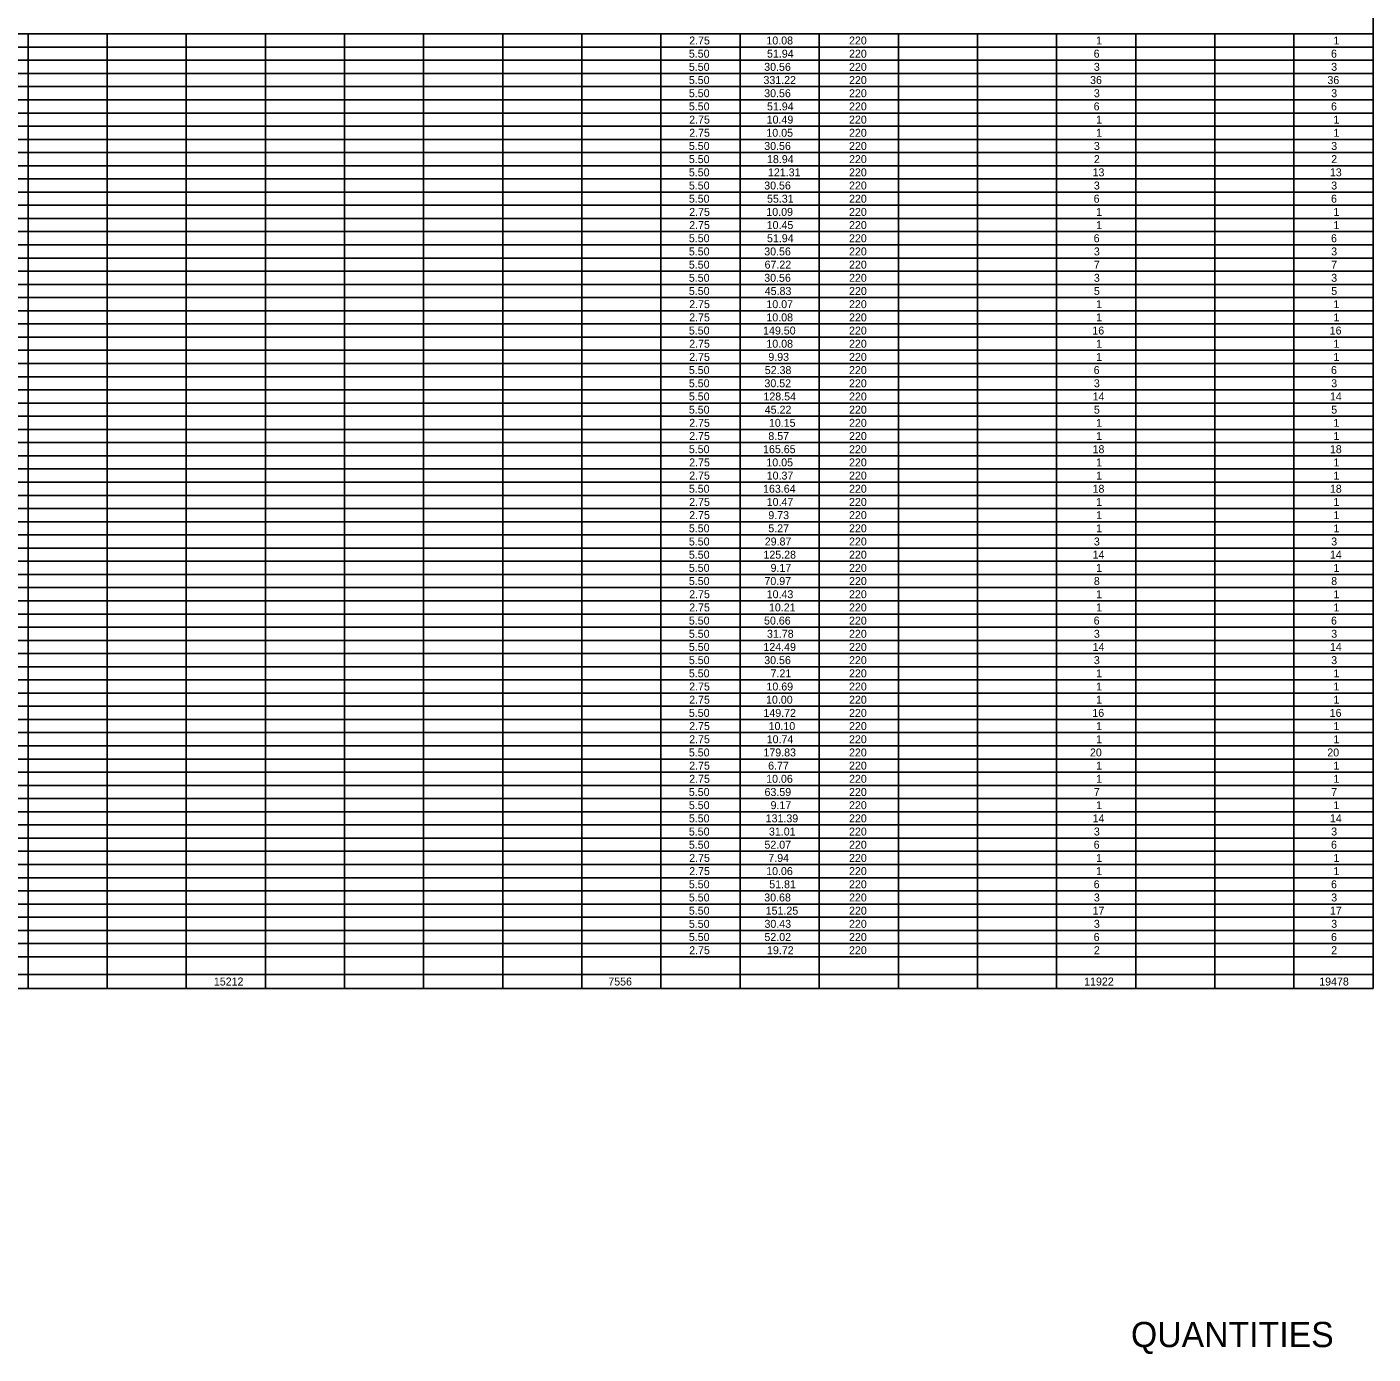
# Model space of a CAD drawing. Extents: x 1226590 to 1228573, y 151304 to 154224.
# Drawn here: x 1227485 to 1228151, y 151304 to 151961 of the extents above; entities that cross this region are included whole.
import ezdxf

# ---------------------------------------------------------------- set-up
doc = ezdxf.new("R2010")
doc.units = 0
doc.layers.add('R_Border Notes', color=7, linetype='Continuous')
doc.layers.add('R_Dimension', color=7, linetype='Continuous')

msp = doc.modelspace()

# ---------------------------------------------------------------- linework, layer by layer
at = {"layer": 'R_Dimension'}
for p, q in [((1228150.73, 151484.92), (1228150.73, 152182.03)), ((1226590.27, 151957.19), (1228150.73, 151957.19)), ((1227485.41, 151484.92), (1227485.41, 151957.19)), ((1227524.55, 151484.92), (1227524.55, 151957.19)), ((1227563.69, 151484.92), (1227563.69, 151957.19)), ((1227602.82, 151484.92), (1227602.82, 151957.19)), ((1227641.96, 151484.92), (1227641.96, 151957.19)), ((1227681.09, 151484.92), (1227681.09, 151957.19)), ((1227720.23, 151484.92), (1227720.23, 151957.19)), ((1227759.37, 151484.92), (1227759.37, 151957.19)), ((1227798.5, 151484.92), (1227798.5, 151957.19)), ((1227837.64, 151484.92), (1227837.64, 151957.19)), ((1227876.78, 151484.92), (1227876.78, 151957.19)), ((1227915.91, 151484.92), (1227915.91, 151957.19)), ((1227955.05, 151484.92), (1227955.05, 151957.19)), ((1227994.18, 151484.92), (1227994.18, 151957.19)), ((1228033.32, 151484.92), (1228033.32, 151957.19)), ((1228072.46, 151484.92), (1228072.46, 151957.19)), ((1228111.59, 151484.92), (1228111.59, 151957.19)), ((1226590.27, 151950.67), (1228150.73, 151950.67)), ((1226590.27, 151944.14), (1228150.73, 151944.14)), ((1226590.27, 151937.62), (1228150.73, 151937.62)), ((1226590.27, 151931.1), (1228150.73, 151931.1)), ((1226590.27, 151924.58), (1228150.73, 151924.58)), ((1226590.27, 151918.05), (1228150.73, 151918.05)), ((1226590.27, 151911.53), (1228150.73, 151911.53)), ((1226590.27, 151905.01), (1228150.73, 151905.01)), ((1226590.27, 151898.48), (1228150.73, 151898.48)), ((1226590.27, 151891.96), (1228150.73, 151891.96)), ((1226590.27, 151885.44), (1228150.73, 151885.44)), ((1226590.27, 151878.92), (1228150.73, 151878.92)), ((1226590.27, 151872.39), (1228150.73, 151872.39)), ((1226590.27, 151865.87), (1228150.73, 151865.87)), ((1226590.27, 151859.35), (1228150.73, 151859.35)), ((1226590.27, 151852.83), (1228150.73, 151852.83)), ((1226590.27, 151846.3), (1228150.73, 151846.3)), ((1226590.27, 151839.78), (1228150.73, 151839.78)), ((1226590.27, 151833.26), (1228150.73, 151833.26)), ((1226590.27, 151826.73), (1228150.73, 151826.73)), ((1226590.27, 151820.21), (1228150.73, 151820.21)), ((1226590.27, 151813.69), (1228150.73, 151813.69)), ((1226590.27, 151807.17), (1228150.73, 151807.17)), ((1226590.27, 151800.64), (1228150.73, 151800.64)), ((1226590.27, 151794.12), (1228150.73, 151794.12)), ((1226590.27, 151787.6), (1228150.73, 151787.6)), ((1226590.27, 151781.08), (1228150.73, 151781.08)), ((1226590.27, 151774.55), (1228150.73, 151774.55)), ((1226590.27, 151768.03), (1228150.73, 151768.03)), ((1226590.27, 151761.51), (1228150.73, 151761.51)), ((1226590.27, 151754.99), (1228150.73, 151754.99)), ((1226590.27, 151748.46), (1228150.73, 151748.46)), ((1226590.27, 151741.94), (1228150.73, 151741.94)), ((1226590.27, 151735.42), (1228150.73, 151735.42)), ((1226590.27, 151728.89), (1228150.73, 151728.89)), ((1226590.27, 151722.37), (1228150.73, 151722.37)), ((1226590.27, 151715.85), (1228150.73, 151715.85)), ((1226590.27, 151709.33), (1228150.73, 151709.33)), ((1226590.27, 151702.8), (1228150.73, 151702.8)), ((1226590.27, 151696.28), (1228150.73, 151696.28)), ((1226590.27, 151689.76), (1228150.73, 151689.76)), ((1226590.27, 151683.24), (1228150.73, 151683.24)), ((1226590.27, 151676.71), (1228150.73, 151676.71)), ((1226590.27, 151670.19), (1228150.73, 151670.19)), ((1226590.27, 151663.67), (1228150.73, 151663.67)), ((1226590.27, 151657.14), (1228150.73, 151657.14)), ((1226590.27, 151650.62), (1228150.73, 151650.62)), ((1226590.27, 151644.1), (1228150.73, 151644.1)), ((1226590.27, 151637.58), (1228150.73, 151637.58)), ((1226590.27, 151631.05), (1228150.73, 151631.05)), ((1226590.27, 151624.53), (1228150.73, 151624.53)), ((1226590.27, 151618.01), (1228150.73, 151618.01)), ((1226590.27, 151611.49), (1228150.73, 151611.49)), ((1226590.27, 151604.96), (1228150.73, 151604.96)), ((1226590.27, 151598.44), (1228150.73, 151598.44)), ((1226590.27, 151591.92), (1228150.73, 151591.92)), ((1226590.27, 151585.4), (1228150.73, 151585.4)), ((1226590.27, 151578.87), (1228150.73, 151578.87)), ((1226590.27, 151572.35), (1228150.73, 151572.35)), ((1226590.27, 151565.83), (1228150.73, 151565.83)), ((1226590.27, 151559.3), (1228150.73, 151559.3)), ((1226590.27, 151552.78), (1228150.73, 151552.78)), ((1226590.27, 151546.26), (1228150.73, 151546.26)), ((1226590.27, 151539.74), (1228150.73, 151539.74)), ((1226590.27, 151533.21), (1228150.73, 151533.21)), ((1226590.27, 151526.69), (1228150.73, 151526.69)), ((1226590.27, 151520.17), (1228150.73, 151520.17)), ((1226590.27, 151513.65), (1228150.73, 151513.65)), ((1226590.27, 151507.12), (1228150.73, 151507.12)), ((1226590.27, 151500.6), (1228150.73, 151500.6)), ((1226590.27, 151491.83), (1228150.75, 151491.83)), ((1226590.27, 151484.92), (1228150.75, 151484.92))]:
    msp.add_line(p, q, dxfattribs=at)

# ---------------------------------------------------------------- texts
at = {"layer": 'R_Border Notes'}
msp.add_text('QUANTITIES', height=12.5, dxfattribs=at).set_placement((1228030.98, 151307.48))
at = {"layer": 'R_Dimension'}
for s, height, p in [('2.75', 3.935, (1227812.46, 151951.96)), ('10.08', 3.935, (1227850.64, 151951.96)), ('220', 3.935, (1227891.52, 151951.96)), ('1', 3.94, (1228013.75, 151951.96)), ('1', 3.94, (1228131.16, 151951.96)), ('5.50', 3.935, (1227812.29, 151945.44)), ('51.94', 3.935, (1227850.95, 151945.44)), ('220', 3.935, (1227891.52, 151945.44)), ('6', 3.94, (1228012.53, 151945.44)), ('6', 3.94, (1228129.94, 151945.44)), ('5.50', 3.935, (1227812.29, 151938.91)), ('30.56', 3.935, (1227849.57, 151938.91)), ('220', 3.935, (1227891.52, 151938.91)), ('3', 3.94, (1228012.64, 151938.91)), ('3', 3.94, (1228130.04, 151938.91)), ('5.50', 3.935, (1227812.29, 151932.39)), ('331.22', 3.935, (1227849.18, 151932.39)), ('220', 3.935, (1227891.52, 151932.39)), ('36', 3.935, (1228010.76, 151932.39)), ('36', 3.935, (1228128.17, 151932.39)), ('5.50', 3.935, (1227812.29, 151925.87)), ('30.56', 3.935, (1227849.57, 151925.87)), ('220', 3.935, (1227891.52, 151925.87)), ('3', 3.94, (1228012.64, 151925.87)), ('3', 3.94, (1228130.04, 151925.87)), ('5.50', 3.935, (1227812.29, 151919.35)), ('51.94', 3.935, (1227850.95, 151919.35)), ('220', 3.935, (1227891.52, 151919.35)), ('6', 3.94, (1228012.53, 151919.35)), ('6', 3.94, (1228129.94, 151919.35)), ('2.75', 3.935, (1227812.46, 151912.82)), ('10.49', 3.935, (1227850.78, 151912.82)), ('220', 3.935, (1227891.52, 151912.82)), ('1', 3.94, (1228013.75, 151912.82)), ('1', 3.94, (1228131.16, 151912.82)), ('2.75', 3.935, (1227812.46, 151906.3)), ('10.05', 3.935, (1227850.64, 151906.3)), ('220', 3.935, (1227891.52, 151906.3)), ('1', 3.94, (1228013.75, 151906.3)), ('1', 3.94, (1228131.16, 151906.3)), ('5.50', 3.935, (1227812.29, 151899.78)), ('30.56', 3.935, (1227849.57, 151899.78)), ('220', 3.935, (1227891.52, 151899.78)), ('3', 3.94, (1228012.64, 151899.78)), ('3', 3.94, (1228130.04, 151899.78)), ('5.50', 3.935, (1227812.29, 151893.26)), ('18.94', 3.935, (1227850.95, 151893.26)), ('220', 3.935, (1227891.52, 151893.26)), ('2', 3.94, (1228012.64, 151893.26)), ('2', 3.94, (1228130.04, 151893.26)), ('5.50', 3.935, (1227812.29, 151886.73)), ('121.31', 3.935, (1227851.41, 151886.73)), ('220', 3.935, (1227891.52, 151886.73)), ('13', 3.935, (1228011.99, 151886.73)), ('13', 3.935, (1228129.39, 151886.73)), ('5.50', 3.935, (1227812.29, 151880.21)), ('30.56', 3.935, (1227849.57, 151880.21)), ('220', 3.935, (1227891.52, 151880.21)), ('3', 3.94, (1228012.64, 151880.21)), ('3', 3.94, (1228130.04, 151880.21)), ('5.50', 3.935, (1227812.29, 151873.69)), ('55.31', 3.935, (1227850.95, 151873.69)), ('220', 3.935, (1227891.52, 151873.69)), ('6', 3.94, (1228012.53, 151873.69)), ('6', 3.94, (1228129.94, 151873.69)), ('2.75', 3.935, (1227812.46, 151867.16)), ('10.09', 3.935, (1227850.62, 151867.16)), ('220', 3.935, (1227891.52, 151867.16)), ('1', 3.94, (1228013.75, 151867.16)), ('1', 3.94, (1228131.16, 151867.16)), ('2.75', 3.935, (1227812.46, 151860.64)), ('10.45', 3.935, (1227850.79, 151860.64)), ('220', 3.935, (1227891.52, 151860.64)), ('1', 3.94, (1228013.75, 151860.64)), ('1', 3.94, (1228131.16, 151860.64)), ('5.50', 3.935, (1227812.29, 151854.12)), ('51.94', 3.935, (1227850.95, 151854.12)), ('220', 3.935, (1227891.52, 151854.12)), ('6', 3.94, (1228012.53, 151854.12)), ('6', 3.94, (1228129.94, 151854.12)), ('5.50', 3.935, (1227812.29, 151847.6)), ('30.56', 3.935, (1227849.57, 151847.6)), ('220', 3.935, (1227891.52, 151847.6)), ('3', 3.94, (1228012.64, 151847.6)), ('3', 3.94, (1228130.04, 151847.6)), ('5.50', 3.935, (1227812.29, 151841.07)), ('67.22', 3.935, (1227849.74, 151841.07)), ('220', 3.935, (1227891.52, 151841.07)), ('7', 3.94, (1228012.64, 151841.07)), ('7', 3.94, (1228130.04, 151841.07)), ('5.50', 3.935, (1227812.29, 151834.55)), ('30.56', 3.935, (1227849.57, 151834.55)), ('220', 3.935, (1227891.52, 151834.55)), ('3', 3.94, (1228012.64, 151834.55)), ('3', 3.94, (1228130.04, 151834.55)), ('5.50', 3.935, (1227812.29, 151828.03)), ('45.83', 3.935, (1227849.83, 151828.03)), ('220', 3.935, (1227891.52, 151828.03)), ('5', 3.94, (1228012.64, 151828.03)), ('5', 3.94, (1228130.04, 151828.03)), ('2.75', 3.935, (1227812.46, 151821.51)), ('10.07', 3.935, (1227850.64, 151821.51)), ('220', 3.935, (1227891.52, 151821.51)), ('1', 3.94, (1228013.75, 151821.51)), ('1', 3.94, (1228131.16, 151821.51)), ('2.75', 3.935, (1227812.46, 151814.98)), ('10.08', 3.935, (1227850.64, 151814.98)), ('220', 3.935, (1227891.52, 151814.98)), ('1', 3.94, (1228013.75, 151814.98)), ('1', 3.94, (1228131.16, 151814.98)), ('5.50', 3.935, (1227812.29, 151808.46)), ('149.50', 3.935, (1227849.01, 151808.46)), ('220', 3.935, (1227891.52, 151808.46)), ('16', 3.935, (1228011.88, 151808.46)), ('16', 3.935, (1228129.29, 151808.46)), ('2.75', 3.935, (1227812.46, 151801.94)), ('10.08', 3.935, (1227850.64, 151801.94)), ('220', 3.935, (1227891.52, 151801.94)), ('1', 3.94, (1228013.75, 151801.94)), ('1', 3.94, (1228131.16, 151801.94)), ('2.75', 3.935, (1227812.46, 151795.42)), ('9.93', 3.935, (1227851.6, 151795.42)), ('220', 3.935, (1227891.52, 151795.42)), ('1', 3.94, (1228013.75, 151795.42)), ('1', 3.94, (1228131.16, 151795.42)), ('5.50', 3.935, (1227812.29, 151788.89)), ('52.38', 3.935, (1227849.83, 151788.89)), ('220', 3.935, (1227891.52, 151788.89)), ('6', 3.94, (1228012.53, 151788.89)), ('6', 3.94, (1228129.94, 151788.89)), ('5.50', 3.935, (1227812.29, 151782.37)), ('30.52', 3.935, (1227849.68, 151782.37)), ('220', 3.935, (1227891.52, 151782.37)), ('3', 3.94, (1228012.64, 151782.37)), ('3', 3.94, (1228130.04, 151782.37)), ('5.50', 3.935, (1227812.29, 151775.85)), ('128.54', 3.935, (1227849.18, 151775.85)), ('220', 3.935, (1227891.52, 151775.85)), ('14', 3.935, (1228011.99, 151775.85)), ('14', 3.935, (1228129.39, 151775.85)), ('5.50', 3.935, (1227812.29, 151769.32)), ('45.22', 3.935, (1227849.83, 151769.32)), ('220', 3.935, (1227891.52, 151769.32)), ('5', 3.94, (1228012.64, 151769.32)), ('5', 3.94, (1228130.04, 151769.32)), ('2.75', 3.935, (1227812.46, 151762.8)), ('10.15', 3.935, (1227851.91, 151762.8)), ('220', 3.935, (1227891.52, 151762.8)), ('1', 3.94, (1228013.75, 151762.8)), ('1', 3.94, (1228131.16, 151762.8)), ('2.75', 3.935, (1227812.46, 151756.28)), ('8.57', 3.935, (1227851.6, 151756.28)), ('220', 3.935, (1227891.52, 151756.28)), ('1', 3.94, (1228013.75, 151756.28)), ('1', 3.94, (1228131.16, 151756.28)), ('5.50', 3.935, (1227812.29, 151749.76)), ('165.65', 3.935, (1227849, 151749.76)), ('220', 3.935, (1227891.52, 151749.76)), ('18', 3.935, (1228011.99, 151749.76)), ('18', 3.935, (1228129.39, 151749.76)), ('2.75', 3.935, (1227812.46, 151743.23)), ('10.05', 3.935, (1227850.64, 151743.23)), ('220', 3.935, (1227891.52, 151743.23)), ('1', 3.94, (1228013.75, 151743.23)), ('1', 3.94, (1228131.16, 151743.23)), ('2.75', 3.935, (1227812.46, 151736.71)), ('10.37', 3.935, (1227850.79, 151736.71)), ('220', 3.935, (1227891.52, 151736.71)), ('1', 3.94, (1228013.75, 151736.71)), ('1', 3.94, (1228131.16, 151736.71)), ('5.50', 3.935, (1227812.29, 151730.19)), ('163.64', 3.935, (1227849, 151730.19)), ('220', 3.935, (1227891.52, 151730.19)), ('18', 3.935, (1228011.99, 151730.19)), ('18', 3.935, (1228129.39, 151730.19)), ('2.75', 3.935, (1227812.46, 151723.67)), ('10.47', 3.935, (1227850.79, 151723.67)), ('220', 3.935, (1227891.52, 151723.67)), ('1', 3.94, (1228013.75, 151723.67)), ('1', 3.94, (1228131.16, 151723.67)), ('2.75', 3.935, (1227812.46, 151717.14)), ('9.73', 3.935, (1227851.6, 151717.14)), ('220', 3.935, (1227891.52, 151717.14)), ('1', 3.94, (1228013.75, 151717.14)), ('1', 3.94, (1228131.16, 151717.14)), ('5.50', 3.935, (1227812.29, 151710.62)), ('5.27', 3.935, (1227851.6, 151710.62)), ('220', 3.935, (1227891.52, 151710.62)), ('1', 3.94, (1228013.75, 151710.62)), ('1', 3.94, (1228131.16, 151710.62)), ('5.50', 3.935, (1227812.29, 151704.1)), ('29.87', 3.935, (1227849.83, 151704.1)), ('220', 3.935, (1227891.52, 151704.1)), ('3', 3.94, (1228012.64, 151704.1)), ('3', 3.94, (1228130.04, 151704.1)), ('5.50', 3.935, (1227812.29, 151697.57)), ('5.50', 3.935, (1227812.29, 151691.05)), ('125.28', 3.935, (1227849.18, 151697.57)), ('9.17', 3.935, (1227852.71, 151691.05)), ('220', 3.935, (1227891.52, 151697.57)), ('220', 3.935, (1227891.52, 151691.05)), ('14', 3.935, (1228011.99, 151697.57)), ('1', 3.94, (1228013.75, 151691.05)), ('14', 3.935, (1228129.39, 151697.57)), ('1', 3.94, (1228131.16, 151691.05)), ('5.50', 3.935, (1227812.29, 151684.53)), ('70.97', 3.935, (1227849.68, 151684.53)), ('220', 3.935, (1227891.52, 151684.53)), ('8', 3.94, (1228012.64, 151684.53)), ('8', 3.94, (1228130.04, 151684.53)), ('2.75', 3.935, (1227812.46, 151678.01)), ('10.43', 3.935, (1227850.79, 151678.01)), ('220', 3.935, (1227891.52, 151678.01)), ('1', 3.94, (1228013.75, 151678.01)), ('1', 3.94, (1228131.16, 151678.01)), ('2.75', 3.935, (1227812.46, 151671.48)), ('10.21', 3.935, (1227851.91, 151671.48)), ('220', 3.935, (1227891.52, 151671.48)), ('1', 3.94, (1228013.75, 151671.48)), ('1', 3.94, (1228131.16, 151671.48)), ('5.50', 3.935, (1227812.29, 151664.96)), ('50.66', 3.935, (1227849.48, 151664.96)), ('220', 3.935, (1227891.52, 151664.96)), ('6', 3.94, (1228012.53, 151664.96)), ('6', 3.94, (1228129.94, 151664.96)), ('5.50', 3.935, (1227812.29, 151658.44)), ('31.78', 3.935, (1227850.95, 151658.44)), ('220', 3.935, (1227891.52, 151658.44)), ('3', 3.94, (1228012.64, 151658.44)), ('3', 3.94, (1228130.04, 151658.44)), ('5.50', 3.935, (1227812.29, 151651.92)), ('124.49', 3.935, (1227849.17, 151651.92)), ('220', 3.935, (1227891.52, 151651.92)), ('14', 3.935, (1228011.99, 151651.92)), ('14', 3.935, (1228129.39, 151651.92)), ('5.50', 3.935, (1227812.29, 151645.39)), ('30.56', 3.935, (1227849.57, 151645.39)), ('220', 3.935, (1227891.52, 151645.39)), ('3', 3.94, (1228012.64, 151645.39)), ('3', 3.94, (1228130.04, 151645.39)), ('5.50', 3.935, (1227812.29, 151638.87)), ('7.21', 3.935, (1227852.71, 151638.87)), ('220', 3.935, (1227891.52, 151638.87)), ('1', 3.94, (1228013.75, 151638.87)), ('1', 3.94, (1228131.16, 151638.87)), ('2.75', 3.935, (1227812.46, 151632.35)), ('10.69', 3.935, (1227850.68, 151632.35)), ('220', 3.935, (1227891.52, 151632.35)), ('1', 3.94, (1228013.75, 151632.35)), ('1', 3.94, (1228131.16, 151632.35)), ('2.75', 3.935, (1227812.46, 151625.83)), ('10.00', 3.935, (1227850.47, 151625.83)), ('220', 3.935, (1227891.52, 151625.83)), ('1', 3.94, (1228013.75, 151625.83)), ('1', 3.94, (1228131.16, 151625.83)), ('5.50', 3.935, (1227812.29, 151619.3)), ('149.72', 3.935, (1227849.18, 151619.3)), ('220', 3.935, (1227891.52, 151619.3)), ('16', 3.935, (1228011.88, 151619.3)), ('16', 3.935, (1228129.29, 151619.3)), ('2.75', 3.935, (1227812.46, 151612.78)), ('10.10', 3.935, (1227851.74, 151612.78)), ('220', 3.935, (1227891.52, 151612.78)), ('1', 3.94, (1228013.75, 151612.78)), ('1', 3.94, (1228131.16, 151612.78)), ('2.75', 3.935, (1227812.46, 151606.26)), ('10.74', 3.935, (1227850.79, 151606.26)), ('220', 3.935, (1227891.52, 151606.26)), ('1', 3.94, (1228013.75, 151606.26)), ('1', 3.94, (1228131.16, 151606.26)), ('5.50', 3.935, (1227812.29, 151599.73)), ('179.83', 3.935, (1227849.18, 151599.73)), ('220', 3.935, (1227891.52, 151599.73)), ('20', 3.935, (1228010.7, 151599.73)), ('20', 3.935, (1228128.11, 151599.73)), ('2.75', 3.935, (1227812.46, 151593.21)), ('6.77', 3.935, (1227851.51, 151593.21)), ('220', 3.935, (1227891.52, 151593.21)), ('1', 3.94, (1228013.75, 151593.21)), ('1', 3.94, (1228131.16, 151593.21)), ('2.75', 3.935, (1227812.46, 151586.69)), ('10.06', 3.935, (1227850.53, 151586.69)), ('220', 3.935, (1227891.52, 151586.69)), ('1', 3.94, (1228013.75, 151586.69)), ('1', 3.94, (1228131.16, 151586.69)), ('5.50', 3.935, (1227812.29, 151580.17)), ('63.59', 3.935, (1227849.72, 151580.17)), ('220', 3.935, (1227891.52, 151580.17)), ('7', 3.94, (1228012.64, 151580.17)), ('7', 3.94, (1228130.04, 151580.17)), ('5.50', 3.935, (1227812.29, 151573.64)), ('9.17', 3.935, (1227852.71, 151573.64)), ('220', 3.935, (1227891.52, 151573.64)), ('1', 3.94, (1228013.75, 151573.64)), ('1', 3.94, (1228131.16, 151573.64)), ('5.50', 3.935, (1227812.29, 151567.12)), ('131.39', 3.935, (1227850.28, 151567.12)), ('220', 3.935, (1227891.52, 151567.12)), ('14', 3.935, (1228011.99, 151567.12)), ('14', 3.935, (1228129.39, 151567.12)), ('5.50', 3.935, (1227812.29, 151560.6)), ('31.01', 3.935, (1227851.91, 151560.6)), ('220', 3.935, (1227891.52, 151560.6)), ('3', 3.94, (1228012.64, 151560.6)), ('3', 3.94, (1228130.04, 151560.6)), ('5.50', 3.935, (1227812.29, 151554.08)), ('52.07', 3.935, (1227849.68, 151554.08)), ('220', 3.935, (1227891.52, 151554.08)), ('6', 3.94, (1228012.53, 151554.08)), ('6', 3.94, (1228129.94, 151554.08)), ('2.75', 3.935, (1227812.46, 151547.55)), ('7.94', 3.935, (1227851.6, 151547.55)), ('220', 3.935, (1227891.52, 151547.55)), ('1', 3.94, (1228013.75, 151547.55)), ('1', 3.94, (1228131.16, 151547.55)), ('2.75', 3.935, (1227812.46, 151541.03)), ('10.06', 3.935, (1227850.53, 151541.03)), ('220', 3.935, (1227891.52, 151541.03)), ('1', 3.94, (1228013.75, 151541.03)), ('1', 3.94, (1228131.16, 151541.03)), ('5.50', 3.935, (1227812.29, 151534.51)), ('51.81', 3.935, (1227852.06, 151534.51)), ('220', 3.935, (1227891.52, 151534.51)), ('6', 3.94, (1228012.53, 151534.51)), ('6', 3.94, (1228129.94, 151534.51)), ('5.50', 3.935, (1227812.29, 151527.98)), ('30.68', 3.935, (1227849.58, 151527.98)), ('220', 3.935, (1227891.52, 151527.98)), ('3', 3.94, (1228012.64, 151527.98)), ('3', 3.94, (1228130.04, 151527.98)), ('5.50', 3.935, (1227812.29, 151521.46)), ('151.25', 3.935, (1227850.3, 151521.46)), ('220', 3.935, (1227891.52, 151521.46)), ('17', 3.935, (1228011.99, 151521.46)), ('17', 3.935, (1228129.39, 151521.46)), ('5.50', 3.935, (1227812.29, 151514.94)), ('30.43', 3.935, (1227849.68, 151514.94)), ('220', 3.935, (1227891.52, 151514.94)), ('3', 3.94, (1228012.64, 151514.94)), ('3', 3.94, (1228130.04, 151514.94)), ('5.50', 3.935, (1227812.29, 151508.42)), ('52.02', 3.935, (1227849.68, 151508.42)), ('220', 3.935, (1227891.52, 151508.42)), ('6', 3.94, (1228012.53, 151508.42)), ('6', 3.94, (1228129.94, 151508.42)), ('2.75', 3.935, (1227812.46, 151501.89)), ('19.72', 3.935, (1227850.95, 151501.89)), ('220', 3.935, (1227891.52, 151501.89)), ('2', 3.94, (1228012.64, 151501.89)), ('2', 3.94, (1228130.04, 151501.89)), ('15212', 3.935, (1227577.32, 151486.4)), ('7556', 3.935, (1227772.43, 151486.4)), ('11922', 3.935, (1228007.82, 151486.4)), ('19478', 3.935, (1228124.12, 151486.4))]:
    msp.add_text(s, height=height, dxfattribs=at).set_placement(p)

doc.saveas('drawing.dxf')
